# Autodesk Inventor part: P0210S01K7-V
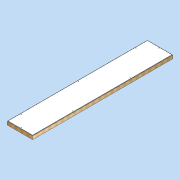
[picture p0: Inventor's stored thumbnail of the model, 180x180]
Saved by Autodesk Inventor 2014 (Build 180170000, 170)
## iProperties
Created: 2011-04
Part Number: P0210S01K7-V
Document SubType Name: Modeling
Designer: david.appleford
Density: 0.217981 g/cm^3
Description: 0.5w x 2.5w 01 Panel - Locks 7
Mass: 28000 g
Surface Area: 37976.1 cm^2
Volume: 128451 cm^3
Cost Center: £114.00
Material: Generic
Appearance: Wood (Pine)
Justset: False
Title: 0.5w x 2.5w 01 Panel - Locks 7
Author: david.appleford
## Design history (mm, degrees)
sketch "Sketch1"
  geometry: L1 (0, 0)-(610, 0); L2 (610, 0)-(610, 3050); L3 (610, 3050)-(0, 3050); L4 (0, 3050)-(0, 0); L5 (34, 3016)-(576, 3016); L6 (576, 3016)-(576, 34); L7 (576, 34)-(34, 34); L8 (34, 34)-(34, 3016)
  constraints: 16 end point, 4 parallel, 2 perpendicular, 1 horizontal, 3 other
  dimensions: "d0" = 610 distance between parallel lines of L2 L4 (= 0.5 x w); "d1" = 3050 distance between parallel lines of L1 L3 (= 2.5 x w); "d2" = 34 distance between parallel lines of L5 L3 (= 0.5 x t)
extrude "Extrusion1" new body sketch "Sketch1" distance "d3" = 68 (= t); taper "d4" = 0 deg
sketch "Sketch2"
  geometry: L1 (576, 3016)-(576, 34) reference; L2 (34, 3016)-(576, 3016) reference; L3 (34, 34)-(34, 3016) reference; L4 (576, 34)-(34, 34) reference; L5 (566, 3006)-(566, 44); L6 (566, 44)-(44, 44); L7 (44, 44)-(44, 3006); L8 (44, 3006)-(566, 3006); 1 further point
  constraints: 8 end point, 3 other
  dimensions: "d5" = 10 distance between parallel lines of L8 L2
extrude "Extrusion2" join sketch "Sketch2" distance "d6" = 6 (= sw); taper "d7" = 0 deg
sketch "Sketch3"
  geometry: L1 (-44, 3006)-(-566, 3006) reference; L2 (-566, 3006)-(-566, 44) reference; L3 (-44, 44)-(-44, 3006) reference; L4 (-566, 44)-(-44, 44) reference; 1 further point
extrude "Extrusion3" join sketch "Sketch3" distance "d8" = 6 (= sw); taper "d9" = 0 deg
sketch "Sketch4"
  geometry: L1 (34, 3016)-(576, 3016) reference; L2 (576, 3016)-(576, 34) reference; L3 (576, 34)-(34, 34) reference; L4 (34, 34)-(34, 3016) reference; 8 further points
  constraints: 3 vertical alignment
  dimensions: "d10" = 28 distance from line of point (305, 2988) L1 (= k); "d12" = 28 distance from line of L3 point (305, 62) (= k); "d13" = 28 distance from line of point (62, 305) L4 (= k); "d14" = 305 horizontal distance of point (305, 2988) point (0, 0) (= 0.25 x w); "d15" = 0 horizontal distance of point (305, 62) point (305, 2988); "d16" = 305 vertical distance of point (62, 305) point (0, 0) (= 0.25 x w); "d17" = 1220 distance of point (62, 305) point (62, 1525) (= w); "d18" = 1220 distance of point (62, 2745) point (62, 1525) (= w); "d19" = 610 vertical distance of point (548, 915) point (62, 305) (= 0.5 x w); "d20" = 1220 distance of point (548, 915) point (548, 2135) (= w); "d29" = 28 distance from line of L2 point (548, 915) (= d13)
hole "Hole1" sketch "Sketch4" at (305, 2988), (62, 2745), (62, 1525), (62, 305), (548, 2135), (548, 915), (305, 62) diameter "d22" = 12 (= hd); stored, may be unused: countersink angle "d26" = 90 deg, drill point angle "d28" = 118 deg; dims "d23" = 6, "d24" = 4, "d25" = 2, "d27" = 8
body "Solid1"
node "Projected Loop1"
other parameters: "w" = 1220 [user parameter; used in 8 equation terms], "t" = 68 [user parameter; used in 2 equation terms], "e" = 16 [user parameter], "sw" = 6 [user parameter; used in 2 equation terms], "sc" = 9 [user parameter], "sf" = 12 [user parameter], "k" = 28 [user parameter; used in 3 equation terms], "hd" = 12 [user parameter; used in 1 equation term]
